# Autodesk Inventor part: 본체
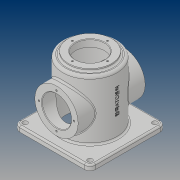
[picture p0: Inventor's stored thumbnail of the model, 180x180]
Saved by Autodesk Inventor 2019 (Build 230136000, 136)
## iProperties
Created: 2019-03
Part Number: 본체
Material: 일반
Document SubType Name: Modeling
Designer: PC312-10
Density: 1 g/cm^3
Appearance: 기본값
Mass: 414.937 g
Surface Area: 1160.05 cm^2
Volume: 414.937 cm^3
Author: PC312-10
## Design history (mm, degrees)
sketch "스케치1"
  geometry: L1 (0, 0)-(0, 120); L2 (0, 112)-(-45, 112); L3 (-45, 112)-(-45, 0); L4 (-45, 0)-(-50, 0); L5 (-50, 0)-(-50, 120); L6 (-50, 120)-(0, 120)
  constraints: 12 end point, 3 horizontal, 3 vertical, 2 point on line
  dimensions: "d0" = 120 distance of L1.end L1.start; "d2" = 100 diameter of L5 L1; "d3" = 90 diameter of L3 L1; "d4" = 112 distance between parallel lines of L4 L2
revolve "회전1" sketch "스케치1" stored, may be unused: angle "d5" = 90 deg
sketch "스케치2"
  geometry: C1 r 40 at (0, 0); 1 further point
  constraints: 1 centre point, 1 coincident
  dimensions: "d6" = 80 diameter of C1
extrude "돌출1" join sketch "스케치2" distance "d7" = 5; taper "d8" = 0 deg
sketch "스케치3"
  geometry: C1 r 40 at (0, 0) reference; C2 r 27 at (0, 0); 1 further point
  constraints: 1 centre point, 1 coincident
  dimensions: "d9" = 54 diameter of C2
extrude "돌출2" cut sketch "스케치3" extent not by distance; stored distance "d10" = 5; taper "d11" = 0 deg
sketch "스케치4"
  geometry: L1 (-70, -70)-(70, -70); L2 (70, -70)-(70, 70); L3 (70, 70)-(-70, 70); L4 (-70, 70)-(-70, -70); L5 (-70, -70)-(70, 70); L6 (70, -70)-(-70, 70); C1 r 50 at (0, 0) reference; 1 further point
  constraints: 12 end point, 2 midpoint, 2 parallel, 1 horizontal, 1 perpendicular
  dimensions: "d12" = 140 distance of L3.end L2.end; "d13" = 140 distance of L2.end L1.end
extrude "돌출3" join sketch "스케치4" distance "d14" = 10; taper "d15" = 0 deg
fillet "모깎기1" dims "d16" = 10
sketch "스케치5"
  geometry: C1 r 4.5 at (-60, 60); C2 r 4.5 at (60, 60); C3 r 4.5 at (60, -60); C4 r 4.5 at (-60, -60); A1 r 10 centre (-60, 60) between (-60, 70) and (-70, 60) reference; A2 r 10 centre (60, 60) between (70, 60) and (60, 70) reference; A3 r 10 centre (60, -60) between (60, -70) and (70, -60) reference; A4 r 10 centre (-60, -60) between (-70, -60) and (-60, -70) reference; 1 further point
  constraints: 4 centre point, 4 coincident
  dimensions: "d17" = 9 diameter of C1; "d18" = 9 diameter of C2; "d19" = 9 diameter of C3; "d20" = 9 diameter of C4
extrude "돌출4" cut sketch "스케치5" extent not by distance; stored distance "d21" = 10; taper "d22" = 0 deg
node "작업 평면1"
sketch "스케치6"
  geometry: L1 (60, 0)-(-60, 0) reference; C1 r 40 at (0, 60); 2 further points
  constraints: 1 centre point, 1 midpoint, 1 vertical alignment
  dimensions: "d24" = 80 diameter of C1; "d25" = 60 distance from line of L1 C1.centre
extrude "돌출5" join sketch "스케치6" stored distance "d26" = 10; taper "d27" = 0 deg
sketch "스케치7"
  geometry: C1 r 40 at (0, 0) reference; C2 r 27 at (0, 0); 1 further point
  constraints: 1 centre point, 1 coincident
  dimensions: "d28" = 54 diameter of C2
extrude "돌출6" cut sketch "스케치7" extent not by distance; stored distance "d29" = 0; taper "d30" = 0 deg
sketch "스케치8"
  geometry: C1 r 40 at (0, 0) reference; 2 further points
  constraints: 1 vertical alignment
  dimensions: "d31" = 32.5 distance of C1.centre point (0, 32.5)
hole "구멍1" sketch "스케치8" at (0, 32.5) diameter "d32" = 3.242; stored, may be unused: countersink angle "d36" = 90 deg, drill point angle "d38" = 118 deg; dims "d33" = 8, "d34" = 4, "d35" = 2, "d37" = 10
sketch "스케치9"
  geometry: 2 further points
  constraints: 1 vertical alignment
  dimensions: "d42" = 32.5 distance of point (0, 0) point (0, 32.5)
hole "구멍2" sketch "스케치9" at (0, 32.5) diameter "d43" = 3.242; stored, may be unused: countersink angle "d47" = 90 deg, drill point angle "d49" = 118 deg; dims "d44" = 8, "d45" = 4, "d46" = 2, "d48" = 10
chamfer "모따기1" distance "d53" = 1; stored, may be unused: second distance "d54" = 2, angle "d55" = 45 deg
fillet "모깎기2" dims "d56" = 3
fillet "모깎기3" dims "d57" = 3
fillet "모깎기4" dims "d58" = 5
fillet "모깎기5" dims "d59" = 3
node "작업 평면2"
sketch "스케치11"
  geometry: L1 (0, -60)-(0, 60) reference; 3 further points
  constraints: 1 horizontal alignment, 1 midpoint, 1 other
  dimensions: "d61" = 70 distance from line of L1 point (70, 0)
feature "엠보싱1" sketch "스케치11" dims "d0" = 120, "d2" = 100, "d3" = 90, "d4" = 112, "d62" = 0.5, "d63" = 0
node "솔리드1"
mirror "미러1"
pattern_circular "원형 패턴1" dims angle "d40" = 360 deg
mirror "미러2"
pattern_circular "원형 패턴2" dims angle "d51" = 360 deg
other parameters: "d23" = 62, "d60" = 83.25
